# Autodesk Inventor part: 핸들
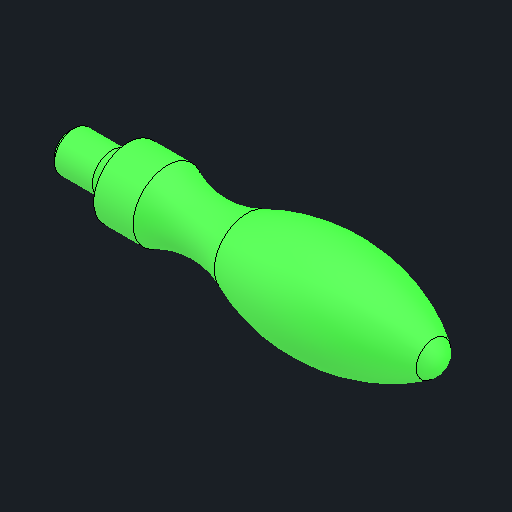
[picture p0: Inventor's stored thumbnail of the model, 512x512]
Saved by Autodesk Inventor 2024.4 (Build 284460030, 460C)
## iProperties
Created: 2026-08
Part Number: 핸들
Material: 스테인리스강
Document SubType Name: Modeling
Designer: user
Density: 8.08 g/cm^3
Appearance: 기본값
Author: jhkim
Sending System: Autodesk Inventor 2027
Preprocessor: ST-DEVELOPER v20.1
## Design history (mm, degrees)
feature "솔리드1"
node "솔리드2"
